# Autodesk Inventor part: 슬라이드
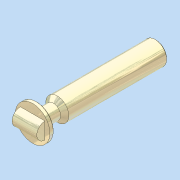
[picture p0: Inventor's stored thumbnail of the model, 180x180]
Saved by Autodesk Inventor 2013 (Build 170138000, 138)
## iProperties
Company: 한국ATC센터
Created: 2014-10
Part Number: 슬라이드
Document SubType Name: Modeling
Designer: 한국ATC센터
Density: 7.86 g/cm^3
Material: 강, 연강
Mass: 702.202 g
Surface Area: 150.69 cm^2
Volume: 89.3387 cm^3
Author: KYOUNG IL JANG
Revision Number: 1
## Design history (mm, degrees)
sketch "스케치1"
  geometry: L1 (-14, 195)-(-14, 171) reference; L2 (19, 106.5)-(-19, 106.5) reference; L3 (0, 106.5)-(0, 256.5); L4 (0, 256.5)-(-14, 256.5); L5 (-14, 256.5)-(-14, 136.5); L6 (-14, 111.5)-(-21, 111.5); L7 (-21, 111.5)-(-21, 106.5); L8 (-21, 106.5)-(0, 106.5); L9 (-14, 111.5)-(-9, 111.5); L10 (-9, 111.5)-(-9, 131.5); L11 (-9, 131.5)-(-14, 136.5); L12 (-14, 136.5)-(-14, 111.5); 1 further point
  constraints: 24 end point, 5 perpendicular, 3 parallel, 1 collinear, 1 horizontal, 1 midpoint, 1 point on line, 1 vertical, 4 other
  dimensions: "d0" = 5 distance between parallel lines of L6 L8; "d1" = 42 diameter of L7 L3; "d2" = 150 distance of L3.start L3.end; "d3" = 135 deg angle of L11 L5; "d4" = 18 diameter of L10 L3; "d5" = 30 distance from line of L5.end L8
revolve "회전1" sketch "스케치1" stored, may be unused: angle "d6" = 90 deg
chamfer "모따기1" distance "d7" = 1; stored, may be unused: second distance "d8" = 2, angle "d9" = 45 deg
fillet "모깎기1" dims "d10" = 2
sketch "스케치2"
  geometry: L1 (21, 106.5)-(-21, 106.5) reference; L2 (-15, 96.5)-(15, 96.5); L3 (15, 96.5)-(15, 106.5); L4 (15, 106.5)-(-15, 106.5); L5 (-15, 106.5)-(-15, 96.5); 2 further points
  constraints: 8 end point, 2 midpoint, 2 parallel, 1 horizontal, 1 perpendicular, 1 point on line
  dimensions: "d11" = 20 diameter of L2 L4; "d12" = 30 distance between parallel lines of L3 L5
revolve "회전2" sketch "스케치2" stored, may be unused: angle "d13" = 180 deg
node "솔리드1"
